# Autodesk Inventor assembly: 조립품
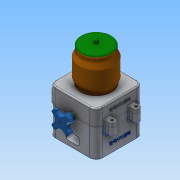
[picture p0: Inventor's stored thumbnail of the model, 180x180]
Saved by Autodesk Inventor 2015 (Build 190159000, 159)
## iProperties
Created: 2018-01
Part Number: 조립품
Document SubType Name: Assembly
Designer: SCD-A18
Author: SCD-A18
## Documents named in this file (9)
- D:\480108V1009\조립품.iam
- D:\480108V1009\본체.ipt
- D:\480108V1009\본체커버.ipt
- D:\480108V1009\볼트 M3x12.ipt
- D:\480108V1009\볼트 M4x12.ipt
- D:\480108V1009\용기.ipt
- D:\480108V1009\용기캡.ipt
- D:\480108V1009\핸들.ipt
- D:\480108V1009\핸들축.ipt
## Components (2 placed, 2 different names)
1. 핸들:1
2. 핸들축:1 — 플러쉬:1
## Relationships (1: Flush 1)
- 플러쉬:1 [Flush]: 핸들축:1
